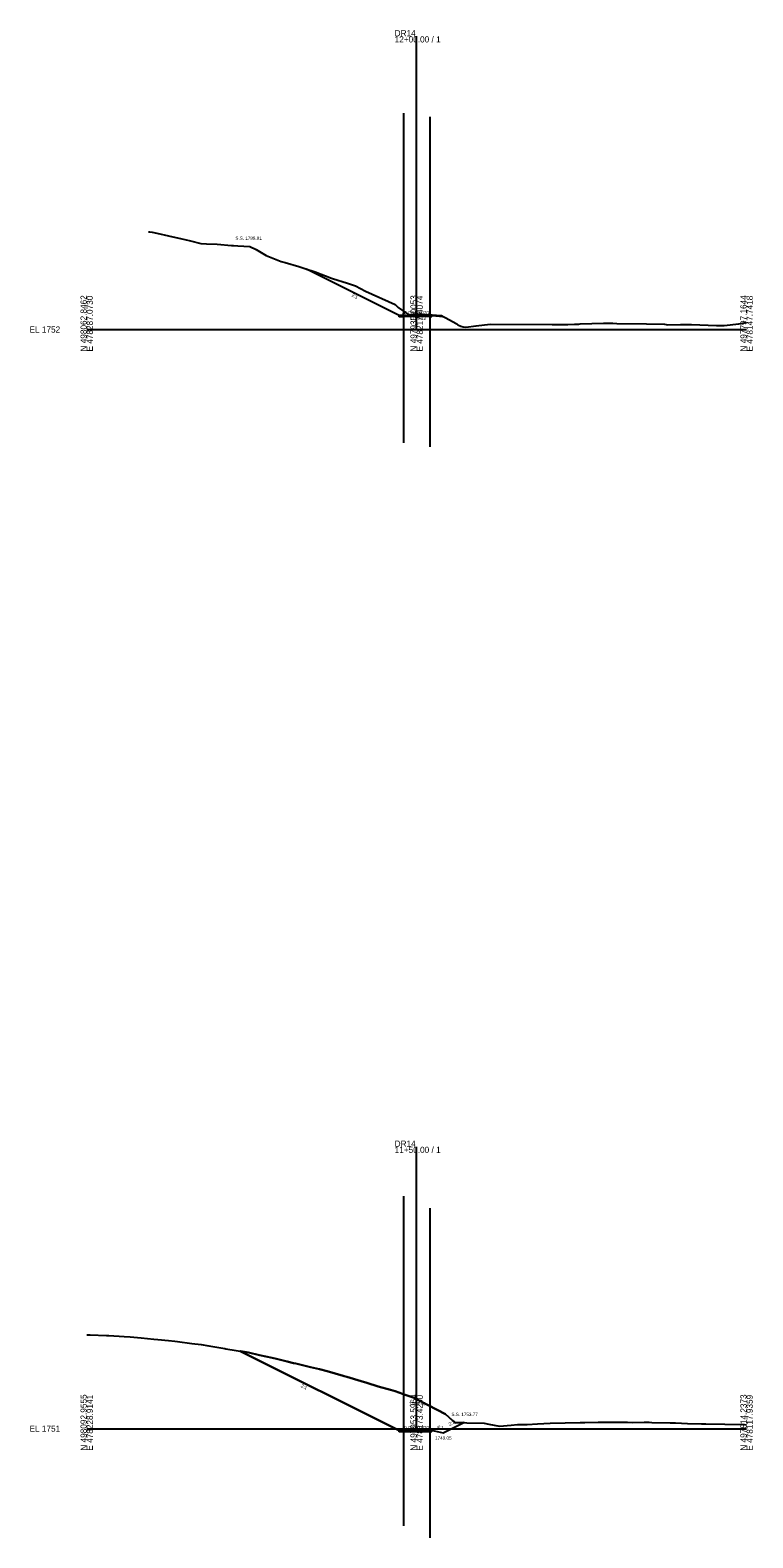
# Model space of a CAD drawing. Extents: x -26 to 303, y -59 to 3067.
# Drawn here: x -26 to 303, y 1450 to 2136 of the extents above; entities that cross this region are included whole.
import ezdxf

# ---------------------------------------------------------------- set-up
doc = ezdxf.new("R2010")
doc.units = 0
for name, color, linetype in [('Exist Cross Section Cell', 7, 'Continuous'), ('Exist XS Center Line Elevation Label', 7, 'Continuous'), ('Exist XS Ground Line', 7, 'Continuous'), ('Prop XS Ditch Slope Text', 7, 'Continuous'), ('Prop XS Ditch Standard Text', 7, 'Continuous'), ('Prop XS Earthwork Shape', 7, 'Continuous'), ('Prop XS EOT Tick Mark', 7, 'Continuous'), ('Prop XS Finish Grade', 7, 'Continuous'), ('Prop XS Finish Grade Earthwork', 7, 'Continuous'), ('Prop XS Finish Grade Pavement', 7, 'Continuous'), ('Prop XS Pvmt Edge Slope', 7, 'Continuous'), ('Prop XS SE Text', 7, 'Continuous'), ('Prop XS Shoulder Borrow Shape', 7, 'Continuous'), ('Prop XS Side Slope Text', 7, 'Continuous'), ('Prop XS SS Elevation Text', 7, 'Continuous'), ('Prop XS Subgrade Earthwork', 7, 'Continuous'), ('Scratch_Level_6', 7, 'Continuous'), ('Typical Curb CELL', 7, 'Continuous')]:
    doc.layers.add(name, color=color, linetype=linetype)

msp = doc.modelspace()

# ---------------------------------------------------------------- linework, layer by layer
at = {"layer": 'Exist Cross Section Cell'}
for p, q in [((150, 2000), (150, 2133.4)), ((0, 2000), (150, 2000)), ((150, 2000), (300, 2000)), ((150, 1500), (150, 1628.25)), ((0, 1500), (150, 1500)), ((150, 1500), (300, 1500))]:
    msp.add_line(p, q, dxfattribs=at)
at = {"layer": 'Exist XS Ground Line'}
for points in [[(28.04, 2044.47), (28.67, 2044.45), (29.73, 2044.32), (31.9, 2043.84), (37.14, 2042.66), (43.2, 2041.24), (44.55, 2040.91), (47.13, 2040.29), (51.96, 2039.18), (54.49, 2039.06), (59.37, 2038.88), (65.78, 2038.28), (66.77, 2038.2), (68.66, 2038.12), (74.18, 2037.72), (77.08, 2036.35), (81.59, 2033.76), (88.37, 2031.02), (89, 2030.79), (90.2, 2030.44), (96.41, 2028.67), (99.67, 2027.56), (103.82, 2026.18), (111.23, 2023.41), (111.73, 2023.26), (118.63, 2021.13), (122.25, 2019.82), (126.74, 2017.47), (140.19, 2011.43), (141.66, 2010), (146.48, 2006.72), (148.77, 2006.96), (150, 2007.12), (150.41, 2007.17), (157.04, 2006.64), (161.2, 2006.34), (162, 2005.92), (162.9, 2005.43), (168.22, 2002.62), (168.71, 2002.17), (170.12, 2001.48), (171.18, 2001.2), (172.35, 2001.06), (176.99, 2001.69), (183.36, 2002.46), (211.57, 2002.28), (217.31, 2002.26), (218.69, 2002.3), (221.81, 2002.41), (223.75, 2002.52), (224.38, 2002.54), (229.61, 2002.73), (234.92, 2002.92), (239.16, 2002.86), (241.03, 2002.8), (254.53, 2002.55), (262.75, 2002.47), (264.24, 2002.12), (269.9, 2002.25), (275.03, 2002.35), (286.34, 2001.82), (289.84, 2001.89), (296.55, 2002.56), (300, 2003.14)], [(0, 1542.75), (1.61, 1542.67), (8.99, 1542.46), (9.31, 1542.45), (10.1, 1542.4), (17.01, 1541.97), (19.76, 1541.75), (24.71, 1541.33), (30.52, 1540.77), (32.41, 1540.52), (37.14, 1540.07), (40.11, 1539.77), (41.29, 1539.66), (47.81, 1538.81), (52.05, 1538.24), (55.51, 1537.68), (62.82, 1536.47), (63.2, 1536.4), (64.18, 1536.24), (70.9, 1535.14), (73.58, 1534.66), (78.6, 1533.4), (84.35, 1532.17), (86.3, 1531.71), (91.21, 1530.54), (94, 1529.87), (95.12, 1529.64), (101.7, 1528.02), (105.88, 1527.09), (109.4, 1526.11), (116.65, 1524.1), (117.1, 1523.95), (118.25, 1523.62), (124.8, 1521.66), (127.41, 1520.88), (132.5, 1519.25), (138.18, 1517.72), (140.2, 1517.08), (145.29, 1515.29), (147.9, 1514.33), (148.94, 1513.97), (150, 1513.43), (155.19, 1510.77), (163.1, 1506.59), (166.26, 1503.79), (167.62, 1502.61), (171.79, 1502.78), (172.75, 1502.74), (180.72, 1502.52), (182.79, 1502.1), (187.74, 1501.2), (193.01, 1501.68), (195.89, 1501.93), (200.2, 1501.95), (204.91, 1502.26), (210.71, 1502.52), (224.3, 1502.85), (224.9, 1502.85), (226.4, 1502.87), (232.6, 1502.97), (235.07, 1502.95), (240.3, 1502.96), (245.83, 1502.92), (248, 1502.85), (253.44, 1502.92), (255.7, 1502.92), (256.86, 1502.88), (265.25, 1502.67), (267.73, 1502.62), (273.07, 1502.35), (279.49, 1502.26), (281.52, 1502.19), (290.08, 1502.06), (298.98, 1501.85), (300, 1501.79)]]:
    msp.add_lwpolyline(points, dxfattribs=at)
at = {"layer": 'Prop XS Earthwork Shape'}
for points in [[(118.63, 2021.13), (122.25, 2019.82), (126.74, 2017.47), (140.19, 2011.43), (141.66, 2010), (146.48, 2006.72), (148.77, 2006.96), (150, 2007.12), (150.41, 2007.17), (157.04, 2006.64), (161.2, 2006.34), (161.92, 2005.96), (157.26, 2006.33), (156.68, 2005.75), (156, 2005.77), (150, 2005.89), (144, 2005.77), (144, 2006.43), (143, 2006.35), (142, 2006.43), (99.9, 2027.48), (103.82, 2026.18), (111.23, 2023.41), (111.73, 2023.26)], [(156, 1498.55), (156.68, 1498.53), (157.26, 1499.11), (158, 1499.05), (162, 1498.05), (171.42, 1502.77), (167.62, 1502.61), (166.26, 1503.79), (163.1, 1506.59), (155.19, 1510.77), (150, 1513.43), (148.94, 1513.97), (147.9, 1514.33), (145.29, 1515.29), (140.2, 1517.08), (138.18, 1517.72), (132.5, 1519.25), (127.41, 1520.88), (124.8, 1521.66), (118.25, 1523.62), (117.1, 1523.95), (116.65, 1524.1), (109.4, 1526.11), (105.88, 1527.09), (101.7, 1528.02), (95.12, 1529.64), (94, 1529.87), (91.21, 1530.54), (86.3, 1531.71), (84.35, 1532.17), (78.6, 1533.4), (73.58, 1534.66), (70.9, 1535.14), (69.77, 1535.33), (142, 1499.21), (143, 1499.13), (144, 1499.21), (144, 1498.55), (150, 1498.67)]]:
    msp.add_lwpolyline(points, close=True, dxfattribs=at)
at = {"layer": 'Prop XS EOT Tick Mark'}
for p, q in [((144, 2006.43), (144, 2007.43)), ((156, 2006.43), (156, 2007.43)), ((144, 1499.21), (144, 1500.21)), ((156, 1499.21), (156, 1500.21))]:
    msp.add_line(p, q, dxfattribs=at)
at = {"layer": 'Prop XS Finish Grade'}
for p, q in [((156, 2006.43), (157.26, 2006.33)), ((156, 1499.21), (157.26, 1499.11))]:
    msp.add_line(p, q, dxfattribs=at)
at = {"layer": 'Prop XS Finish Grade Earthwork'}
for p, q in [((142, 2006.43), (99.9, 2027.48)), ((142, 2006.43), (143, 2006.35)), ((143, 2006.35), (144, 2006.43)), ((157.26, 2006.33), (161.92, 2005.96)), ((142, 1499.21), (69.77, 1535.33)), ((162, 1498.05), (171.42, 1502.77)), ((142, 1499.21), (143, 1499.13)), ((143, 1499.13), (144, 1499.21)), ((157.26, 1499.11), (158, 1499.05)), ((158, 1499.05), (162, 1498.05))]:
    msp.add_line(p, q, dxfattribs=at)
at = {"layer": 'Prop XS Finish Grade Pavement'}
for p, q in [((144, 2006.43), (150, 2006.55)), ((150, 2006.55), (156, 2006.43)), ((144, 1499.21), (150, 1499.33)), ((150, 1499.33), (156, 1499.21))]:
    msp.add_line(p, q, dxfattribs=at)
at = {"layer": 'Prop XS Pvmt Edge Slope'}
for p, q in [((156, 2006.43), (156.68, 2005.75)), ((156, 1499.21), (156.68, 1498.53))]:
    msp.add_line(p, q, dxfattribs=at)
at = {"layer": 'Prop XS Shoulder Borrow Shape'}
for p, q in [((157.26, 2006.33), (156, 2006.43)), ((156, 2006.43), (156.68, 2005.75)), ((156.68, 2005.75), (157.26, 2006.33)), ((156, 1499.21), (156.68, 1498.53)), ((157.26, 1499.11), (156, 1499.21)), ((156, 1499.21), (156, 1499.21)), ((156.68, 1498.53), (157.26, 1499.11))]:
    msp.add_line(p, q, dxfattribs=at)
at = {"layer": 'Prop XS Subgrade Earthwork'}
for p, q in [((144, 2005.77), (144, 2006.43)), ((150, 2005.89), (144, 2005.77)), ((156, 2005.77), (150, 2005.89)), ((156, 2005.77), (156.68, 2005.75)), ((156.68, 2005.75), (157.26, 2006.33)), ((144, 1498.55), (144, 1499.21)), ((150, 1498.67), (144, 1498.55)), ((156, 1498.55), (150, 1498.67)), ((156, 1498.55), (156.68, 1498.53)), ((156.68, 1498.53), (157.26, 1499.11))]:
    msp.add_line(p, q, dxfattribs=at)
at = {"layer": 'Scratch_Level_6'}
for p, q in [((144, 2098.41), (144, 1948.41)), ((156, 2096.72), (156, 1946.72)), ((144, 1605.74), (144, 1455.74)), ((156, 1600.35), (156, 1450.35))]:
    msp.add_line(p, q, dxfattribs=at)
at = {"layer": 'Typical Curb CELL'}
for p, q in [((142, 2006.43), (143, 2006.35)), ((142, 2005.85), (142, 2006.43)), ((144, 2005.85), (142, 2005.85)), ((142.17, 2006.2), (142.26, 2006.32)), ((142.29, 2006.21), (142.17, 2006.2)), ((142.26, 2006.32), (142.29, 2006.21)), ((142.53, 2005.96), (142.59, 2006.08)), ((142.69, 2006), (142.53, 2005.96)), ((142.59, 2006.08), (142.69, 2006)), ((144, 2006.43), (143, 2006.35)), ((143.22, 2006.16), (143.3, 2006.28)), ((143.34, 2006.16), (143.22, 2006.16)), ((143.3, 2006.28), (143.34, 2006.16)), ((143.74, 2005.92), (143.82, 2006.04)), ((143.86, 2005.93), (143.74, 2005.92)), ((143.82, 2006.04), (143.86, 2005.93)), ((144, 2005.85), (144, 2006.43)), ((142, 1499.21), (143, 1499.13)), ((142, 1498.63), (142, 1499.21)), ((144, 1498.63), (142, 1498.63)), ((142.17, 1498.98), (142.26, 1499.1)), ((142.29, 1498.99), (142.17, 1498.98)), ((142.26, 1499.1), (142.29, 1498.99)), ((142.53, 1498.74), (142.59, 1498.86)), ((142.69, 1498.78), (142.53, 1498.74)), ((142.59, 1498.86), (142.69, 1498.78)), ((144, 1499.21), (143, 1499.13)), ((143.22, 1498.94), (143.3, 1499.06)), ((143.34, 1498.95), (143.22, 1498.94)), ((143.3, 1499.06), (143.34, 1498.95)), ((143.74, 1498.7), (143.82, 1498.82)), ((143.86, 1498.71), (143.74, 1498.7)), ((143.82, 1498.82), (143.86, 1498.71)), ((144, 1498.63), (144, 1499.21))]:
    msp.add_line(p, q, dxfattribs=at)
for centre in [(142.06, 2005.93), (142.1, 2006.33), (142.12, 2005.89), (142.14, 2006.09), (142.15, 2006.02), (142.26, 2005.93), (142.43, 2006.07), (142.5, 2006.3), (142.72, 2006.29), (142.75, 2006.14), (142.81, 2006.1), (142.84, 2006.23), (142.87, 2006.02), (143.07, 2006.24), (143.12, 2005.99), (143.18, 2005.95), (143.21, 2006.08), (143.36, 2005.94), (143.47, 2006.29), (143.53, 2006.12), (143.59, 2006.08), (143.62, 2006.21), (143.68, 2005.93), (143.7, 2006.21), (143.75, 2006.24), (143.79, 2006.12), (143.91, 2005.97), (143.99, 2006.16), (142.06, 1498.71), (142.1, 1499.11), (142.12, 1498.67), (142.14, 1498.87), (142.15, 1498.8), (142.26, 1498.71), (142.43, 1498.85), (142.5, 1499.08), (142.72, 1499.07), (142.75, 1498.92), (142.81, 1498.89), (142.84, 1499.01), (142.87, 1498.8), (143.07, 1499.03), (143.12, 1498.77), (143.18, 1498.73), (143.21, 1498.86), (143.36, 1498.72), (143.47, 1499.08), (143.53, 1498.9), (143.59, 1498.86), (143.62, 1498.99), (143.68, 1498.71), (143.7, 1498.99), (143.75, 1499.02), (143.79, 1498.9), (143.91, 1498.75), (143.99, 1498.94)]:
    msp.add_circle(centre, 0.00802, dxfattribs=at)

# ---------------------------------------------------------------- texts
at = {"layer": 'Exist Cross Section Cell'}
for s, p in [('12+00.00 / 1', (140, 2130.6)), ('DR14', (140, 2133.4)), ('EL 1752', (-26, 1998.6)), ('11+50.00 / 1', (140, 1625.45)), ('DR14', (140, 1628.25)), ('EL 1751', (-26, 1498.6))]:
    msp.add_text(s, height=2.8, dxfattribs=at).set_placement(p)
for s, p in [('N 498062.8462', (0, 1990)), ('E 478287.0730', (2.8, 1990)), ('N 497930.0053', (150, 1990)), ('E 478217.4074', (152.8, 1990)), ('N 497797.1644', (300, 1990)), ('E 478147.7418', (302.8, 1990)), ('N 498092.9555', (0, 1490)), ('E 478228.9141', (2.8, 1490)), ('N 497953.5964', (150, 1490)), ('E 478173.4250', (152.8, 1490)), ('N 497814.2373', (300, 1490)), ('E 478117.9359', (302.8, 1490))]:
    msp.add_text(s, height=2.8, rotation=90, dxfattribs=at).set_placement(p)
at = {"layer": 'Exist XS Center Line Elevation Label'}
for s, p in [('1759.12', (146.82, 2004.37)), ('1764.43', (146.55, 1510.68))]:
    msp.add_text(s, height=1.5, dxfattribs=at).set_placement(p)
at = {"layer": 'Prop XS Ditch Slope Text'}
msp.add_text('4:1', height=1.5, rotation=345.96376, dxfattribs=at).set_placement((159.21, 1500.3))
at = {"layer": 'Prop XS Ditch Standard Text'}
msp.add_text('1749.05', height=1.5, dxfattribs=at).set_placement((158.39, 1495.05))
at = {"layer": 'Prop XS SE Text'}
for rotation, p in [(1.14576, (144.38, 2006.94)), (358.85424, (150.38, 2007.04)), (1.14576, (144.38, 1499.72)), (358.85424, (150.38, 1499.83))]:
    msp.add_text('0.020', height=1.5, rotation=rotation, dxfattribs=at).set_placement(p)
at = {"layer": 'Prop XS Side Slope Text'}
for rotation, p in [(333.43495, (120.28, 2015.15)), (333.43495, (97.22, 1519.02)), (26.56505, (164.98, 1501.22))]:
    msp.add_text('2:1', height=1.5, rotation=rotation, dxfattribs=at).set_placement(p)
at = {"layer": 'Prop XS SS Elevation Text'}
for s, p in [('S.S. 1789.81', (67.6, 2040.81)), ('S.S. 1753.77', (165.82, 1505.77))]:
    msp.add_text(s, height=1.5, dxfattribs=at).set_placement(p)

doc.saveas('drawing.dxf')
